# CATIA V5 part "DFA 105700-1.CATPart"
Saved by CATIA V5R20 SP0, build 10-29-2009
Part number: DFA 105700-1
Revision: ANY
Definition: UNKNOWN
Nomenclature: DFA 105700-1
Source: Unknown
Bounding box of the stored display mesh (mm): x -2.853 to 2.853, y 0.2 to 2.5, z -3 to 3
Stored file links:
  C:\Users\Utente\Desktop\IO LAVORO\3D X SITO CF\CUMSA\3D files FA\FA 105706-21\DFA 105700-1.CATPart
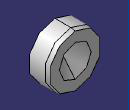
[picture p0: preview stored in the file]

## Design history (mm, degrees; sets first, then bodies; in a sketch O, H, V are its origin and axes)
Body1 "Cortar-Extruir1" (main body)
  Solid1: solid without history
